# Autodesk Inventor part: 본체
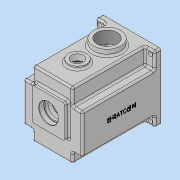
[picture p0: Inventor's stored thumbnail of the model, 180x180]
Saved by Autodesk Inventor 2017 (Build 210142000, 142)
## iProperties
Part Number: 본체
Material: 일반
Document SubType Name: Modeling
Designer: MRC
Density: 1 g/cm^3
Appearance: 기본값
Author: MRC
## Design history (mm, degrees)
sketch "스케치1"
  geometry: L1 (-49, 60)-(49, 60); L2 (49, 60)-(49, -50); L3 (49, -50)-(-49, -50); L4 (-49, -50)-(-49, 60); 2 further points
  constraints: 8 end point, 2 parallel, 1 horizontal, 1 midpoint, 1 perpendicular, 1 vertical alignment
  dimensions: "d0" = 98 distance of L2.end L3.end; "d1" = 110 distance of L1.end L2.end; "d2" = 50 distance from line of L3 point (0, 0)
extrude "돌출1" new body sketch "스케치1" distance "d3" = 130; taper "d4" = 0 deg
sketch "스케치2"
  geometry: L1 (33, 60)-(49, 60); L2 (49, 60)-(49, 33); L3 (49, 33)-(33, 33); L4 (33, 33)-(33, 60); L5 (-49, -50)-(49, -50) reference; L6 (49, -50)-(33, -50); L7 (33, -50)-(33, -33); L8 (33, -33)-(49, -33); L9 (49, -33)-(49, -50); 2 further points
  constraints: 16 end point, 4 parallel, 2 horizontal, 2 perpendicular, 1 coincident
  dimensions: "d5" = 17 distance of L8.end L5.end; "d6" = 27 distance of L1.end L2.end; "d7" = 16 distance of L1.start L1.end; "d8" = 16 distance of L7.end L8.end
extrude "돌출2" cut sketch "스케치2" distance "d9" = 120; taper "d10" = 0 deg
sketch "스케치3"
  geometry: L1 (-27, 38)-(27, 38); L2 (27, 38)-(27, -16); L3 (27, -16)-(-27, -16); L4 (-27, -16)-(-27, 38); 2 further points
  constraints: 8 end point, 2 parallel, 1 horizontal, 1 midpoint, 1 perpendicular, 1 vertical alignment
  dimensions: "d11" = 54 distance of L1.end L2.end; "d12" = 54 distance of L1.start L1.end; "d13" = 38 distance from line of point (0, 0) L1
fillet "모깎기1" dims "d17" = 3
fillet "모깎기2" dims "d18" = 3
fillet "모깎기3" dims "d19" = 3
extrude "돌출3" join sketch "스케치3" distance "d20" = 7; taper "d21" = 0 deg
fillet "모깎기4" dims "d22" = 3
fillet "모깎기5" dims "d23" = 3
sketch "스케치4"
  geometry: L1 (0, 0)-(92, 0) reference; C1 r 15 at (46, -89); C2 r 22.5 at (46, -40); 3 further points
  constraints: 2 centre point, 2 midpoint, 2 vertical alignment
  dimensions: "d24" = 40 distance from line of C2.centre L1; "d25" = 49 distance of C1.centre C2.centre; "d26" = 30 diameter of C1; "d27" = 45 diameter of C2
extrude "돌출4" join sketch "스케치4" distance "d28" = 10; taper "d29" = 0 deg
extrude "돌출5" join sketch "스케치4" distance "d30" = 5; taper "d31" = 0 deg
sketch "스케치5"
  geometry: L1 (-23, 35.143)-(-23, 50); L2 (-23, 50)-(23, 50); L3 (23, 50)-(23, 35.143); A1 r 42 centre (0, 0) between (-23, 35.143) and (23, 35.143); 2 further points
  constraints: 6 end point, 2 point on circle, 2 vertical, 1 centre point, 1 coincident, 1 midpoint, 1 perpendicular, 1 vertical alignment
  dimensions: "d34" = 84 diameter of A1; "d35" = 46 distance of L1.end L2.end; "d36" = 50 distance from line of L2 point (0, 0)
extrude "돌출6" cut sketch "스케치5" distance "d37" = 121; taper "d38" = 0 deg
fillet "모깎기6" dims "d39" = 6
fillet "모깎기7" dims "d40" = 3
fillet "모깎기8" dims "d41" = 3
sketch "스케치6"
  geometry: L1 (49, -47)-(49, 57) reference; L2 (46, 60)-(-46, 60) reference; L3 (-49, 57)-(-49, -47) reference; L4 (-46, -50)-(46, -50) reference; L5 (-23, 38.249)-(-23, 47) reference; L6 (-20, 50)-(20, 50) reference; L7 (23, 47)-(23, 38.249) reference; L8 (26, 38.249)-(26, 47); L9 (20, 53)-(-20, 53); L10 (-26, 47)-(-26, 38.249); A1 r 3 centre (46, -47) between (46, -50) and (49, -47) reference; A2 r 3 centre (46, 57) between (49, 57) and (46, 60) reference; A3 r 3 centre (-46, 57) between (-46, 60) and (-49, 57) reference; A4 r 3 centre (-46, -47) between (-49, -47) and (-46, -50) reference; A5 r 6 centre (29, 38.249) between (23, 38.249) and (25.375, 33.468) reference; A6 r 42 centre (0, 0) between (-25.375, 33.468) and (25.375, 33.468) reference; A7 r 6 centre (-29, 38.249) between (-25.375, 33.468) and (-23, 38.249) reference; A8 r 3 centre (-20, 47) between (-20, 50) and (-23, 47) reference; A9 r 3 centre (20, 47) between (23, 47) and (20, 50) reference; A10 r 3 centre (29, 38.249) between (26, 38.249) and (27.188, 35.859); A11 r 6 centre (20, 47) between (26, 47) and (20, 53); A12 r 6 centre (-20, 47) between (-20, 53) and (-26, 47); A13 r 3 centre (-29, 38.249) between (-27.188, 35.859) and (-26, 38.249); A14 r 45 centre (0, 0) between (-27.188, 35.859) and (27.188, 35.859); 1 further point
  constraints: 10 point on circle, 6 end point, 5 centre point, 7 other
  dimensions: "d42" = 3 radial gap between concentric circles of A6 A14
extrude "돌출7" cut sketch "스케치6" distance "d43" = 9; taper "d44" = 0 deg
sketch "스케치7"
  geometry: A1 r 21 centre (0, 11) between (8.978, -7.984) and (-8.978, -7.984); A2 r 15 centre (0, -20) between (-8.978, -7.984) and (8.978, -7.984); 1 further point
  constraints: 4 point on circle, 2 centre point, 2 vertical alignment
  dimensions: "d45" = 42 diameter of A1; "d46" = 30 diameter of A2; "d47" = 11 distance of point (0, 0) A1.centre; "d48" = 20 distance of point (0, 0) A2.centre
extrude "돌출8" join sketch "스케치7" distance "d49" = 7; taper "d50" = 0 deg
fillet "모깎기9" dims "d51" = 3
fillet "모깎기10" dims "d52" = 3
sketch "스케치8"
  geometry: C1 r 17.5 at (0, 11); A1 r 21 centre (0, 11) between (12.163, -6.119) and (-12.163, -6.119) reference; 1 further point
  constraints: 1 centre point, 1 concentric
  dimensions: "d53" = 35 diameter of C1
extrude "돌출9" cut sketch "스케치8" distance "d54" = 10; taper "d55" = 0 deg
hole "구멍1" diameter "d58" = 19; stored, may be unused: countersink angle "d62" = 90 deg, drill point angle "d64" = 0 deg; dims "d56" = 10, "d57" = 10, "d59" = 6, "d60" = 22, "d61" = 7, "d63" = 10
fillet "모깎기11" dims "d65" = 3
sketch "스케치9"
  geometry: 2 further points
  constraints: 1 vertical alignment
  dimensions: "d66" = 11 distance of point (0, 0) point (0, 11)
hole "구멍2" sketch "스케치9" at (0, 11) diameter "d67" = 28; stored, may be unused: countersink angle "d71" = 90 deg, drill point angle "d73" = 0 deg; dims "d68" = 6, "d69" = 32, "d70" = 8.3, "d72" = 10
fillet "모깎기12" dims "d74" = 0.3
chamfer "모따기1" distance "d75" = 1; stored, may be unused: second distance "d76" = 2, angle "d77" = 45 deg
chamfer "모따기2" distance "d78" = 0.8; stored, may be unused: second distance "d79" = 2, angle "d80" = 30 deg
fillet "모깎기13" dims "d81" = 3
sketch "스케치10"
  geometry: C1 r 10 at (0, 0); C2 r 15 at (0, 0) reference; 1 further point
  constraints: 1 centre point, 1 concentric
  dimensions: "d82" = 20 diameter of C1
extrude "돌출10" cut sketch "스케치10" stored distance "d83" = 10; taper "d84" = 0 deg
sketch "스케치11"
  geometry: C1 r 15 at (20, -29); C2 r 10 at (20, -29) reference; 1 further point
  constraints: 1 centre point, 1 concentric
  dimensions: "d85" = 30 diameter of C1
extrude "돌출11" cut sketch "스케치11" distance "d86" = 5; taper "d87" = 0 deg
chamfer "모따기3" distance "d88" = 1; stored, may be unused: second distance "d89" = 2, angle "d90" = 30 deg
hole "구멍3" diameter "d93" = 33.376; stored, may be unused: countersink angle "d97" = 90 deg, drill point angle "d99" = 0 deg; dims "d91" = 10, "d92" = 10, "d94" = 70, "d95" = 32, "d96" = 8.3, "d98" = 77.3
sketch "스케치12"
  geometry: L1 (36, 4)-(41.809, 4); L2 (36, -4)-(41.809, -4); A1 r 4 centre (36, 0) between (36, 4) and (36, -4); A2 r 42 centre (0, 0) between (-25.375, 33.468) and (25.375, 33.468) reference; 1 further point
  constraints: 4 end point, 4 point on circle, 2 horizontal, 2 tangent, 1 centre point, 1 horizontal alignment
  dimensions: "d100" = 8 diameter of A1; "d101" = 36 distance of A1.centre point (0, 0)
extrude "돌출12" join sketch "스케치12" stored distance "d102" = 5; taper "d103" = 0 deg
hole "구멍4" diameter "d106" = 3.242; stored, may be unused: countersink angle "d110" = 90 deg, drill point angle "d112" = 118 deg; dims "d104" = 10, "d105" = 10, "d107" = 7, "d108" = 32, "d109" = 8.3, "d111" = 9
fillet "모깎기14" dims "d113" = 3
sketch "스케치13"
  geometry: L1 (-49, 57)-(-49, -47) reference; L2 (-46, -50)-(46, -50) reference; C1 r 3.5 at (-42, -43); 1 further point
  constraints: 1 centre point
  dimensions: "d114" = 7 diameter of C1; "d115" = 7 distance from line of L1 C1.centre; "d116" = 7 distance from line of C1.centre L2
extrude "돌출13" cut sketch "스케치13" stored distance "d117" = 5; taper "d118" = 0 deg
sketch "스케치14"
  geometry: L1 (-130, 104)-(-130, 83) reference; 2 further points
  constraints: 1 horizontal alignment, 1 other
  dimensions: "d125" = 65 distance from line of point (-65, 47) L1
feature "엠보싱1" sketch "스케치14" dims "d126" = 0.5, "d127" = 0
node "솔리드1"
mirror "미러1"
mirror "미러2"
pattern_linear "직사각형 패턴1" dims "d121" = 84, "d124" = 96
node "투영된 루프1"
